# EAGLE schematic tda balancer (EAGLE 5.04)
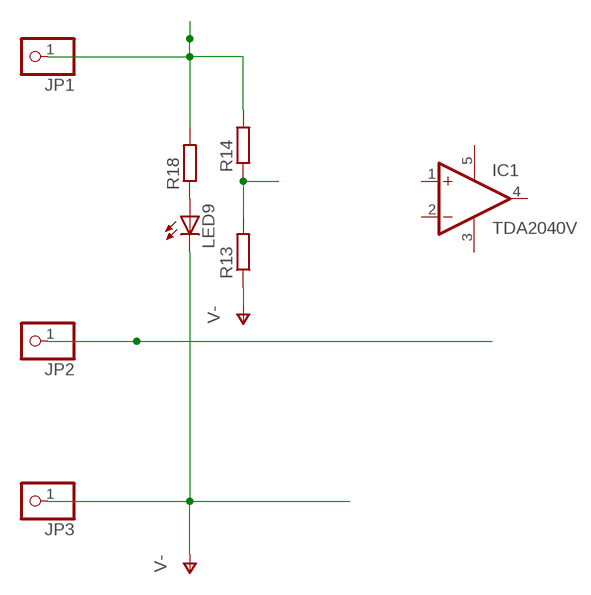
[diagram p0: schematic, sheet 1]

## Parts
IC1  TDA2040V  [CB360]
JP1  PINHD-1X1  [1X01]
JP2  PINHD-1X1  [1X01]
JP3  PINHD-1X1  [1X01]
LED9  LED3MM  [LED3MM]
R13  R-EU_0204/5  [0204/5]
R14  R-EU_0204/5  [0204/5]
R18  R-EU_0204/5  [0204/5]

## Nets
B1: JP2.1
N$28: R13.2 R14.1
N$34: LED9.A R18.1
V+: JP1.1 R14.2 R18.2
V-: JP3.1 LED9.K(C) R13.1
Unconnected: IC1.1(+IN) IC1.2(-IN) IC1.4(OUT)

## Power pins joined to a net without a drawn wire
V+: IC1.5(V+)
V-: IC1.3(V-)

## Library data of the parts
IC1 = linear:TDA2040: Power OP AMP
JP1-JP3 = pinhead:PINHD-1X1: PIN HEADER
LED9 = led:LED: LED
R13 R14 R18 = rcl-2:R-EU_: RESISTOR, European symbol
